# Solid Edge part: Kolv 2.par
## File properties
Author: Türk
Template: Iso Part.par
Last saved by: Türk
Revision: 13
Application: Solid Edge
Accuracy: 0,990
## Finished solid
Body 1: sheet body, 3 faces, 60 edges, 60 vertices.
  Faces by surface: plane 3
  Edges by curve: line 60
Body 2: solid body, 57 faces, 112 edges, 56 vertices.
  Faces by surface: plane 32, cylinder 16, cone 9
  Edges by curve: line 52, circle 44, ellipse 12, intersection 4
Bounding box of the edges (mm): 88.000 x 88.000 x 65.000, from (-44, -44, -25) to (44, 44, 40).
Cylindrical faces by radius (mm): R2.5 x4, R10 x2, R37.5 x1, R39 x2, R41.5 x3, R44 x4
Conical faces (half-angle, radius in mm at the cone's reference point): 45 deg R2.5 x4, 45 deg R37.5 x1, 45 deg R38.7 x1, 45 deg R39 x1, 45 deg R44 x1, 45 deg R49 x1
Planar faces by outward normal: +x 1, +y 2, +z 9, -x 1, -y 2, -z 5, oblique 12
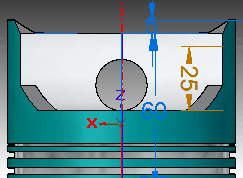
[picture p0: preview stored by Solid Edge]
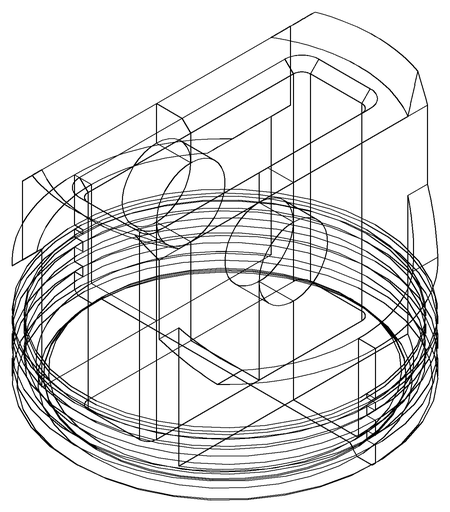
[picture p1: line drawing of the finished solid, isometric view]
